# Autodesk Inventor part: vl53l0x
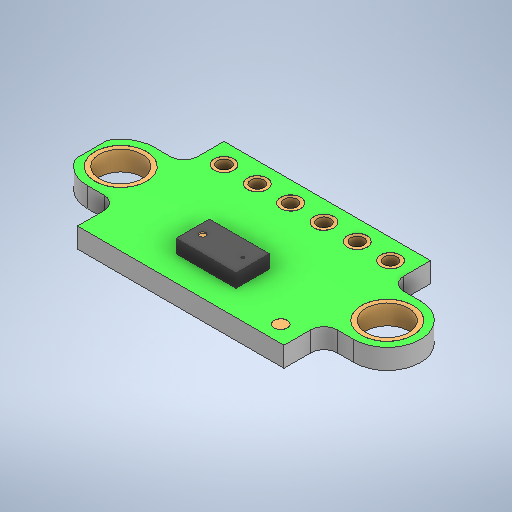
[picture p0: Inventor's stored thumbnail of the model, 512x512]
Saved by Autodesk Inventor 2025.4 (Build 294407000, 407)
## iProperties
Created: 2018-10
Part Number: vl53l0x
Material: Generic
Document SubType Name: Modeling
Designer: Marcio Valenzuela
Density: 1 g/cm^3
Appearance: Default
Sending System: CREO PARAMETRIC BY PTC INC, 2018100
Preprocessor: CREO PARAMETRIC BY PTC INC, 2018100
Title: VL53L0X
Author: Davor
Revision Number: 1LAST_VERSION
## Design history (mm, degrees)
feature "Base1"
body "Solid1"
